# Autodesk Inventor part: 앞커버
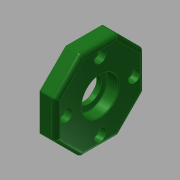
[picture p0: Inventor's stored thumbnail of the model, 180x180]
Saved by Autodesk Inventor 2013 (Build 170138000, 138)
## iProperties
Created: 2015-11
Part Number: 앞커버
Material: 알루미늄 6061
Document SubType Name: Modeling
Designer: mduedu
Density: 2.71 g/cm^3
Mass: 74.9225 g
Surface Area: 93.0141 cm^2
Volume: 27.6467 cm^3
Author: mduedu
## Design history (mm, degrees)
sketch "스케치5" dims "d66" = 60
  geometry: L1 (12.426, 30)-(30, 12.426); L2 (30, 12.426)-(30, -12.426); L3 (30, -12.426)-(12.426, -30); L4 (12.426, -30)-(-12.426, -30); L5 (-12.426, -30)-(-30, -12.426); L6 (-30, -12.426)-(-30, 12.426); L7 (-30, 12.426)-(-12.426, 30); L8 (-12.426, 30)-(12.426, 30); 4 further points
  constraints: 16 end point, 2 coincident, 2 vertical alignment, 1 midpoint, 19 other
extrude "돌출2" new body sketch "스케치5" distance "d67" = 11; taper "d68" = 0 deg
sketch "스케치6"
  geometry: C1 r 16 at (0, 0); 1 further point
  constraints: 1 centre point, 1 coincident
  dimensions: "d69" = 32 diameter of C1
extrude "돌출3" join sketch "스케치6" distance "d70" = 3; taper "d71" = 0 deg
hole "구멍7" diameter "d98" = 25; stored, may be unused: countersink angle "d102" = 90 deg, drill point angle "d104" = 0 deg; dims "d96" = 10, "d97" = 10, "d99" = 6, "d100" = 4, "d101" = 2, "d103" = 3
hole "구멍8" diameter "d107" = 25; stored, may be unused: countersink angle "d111" = 90 deg, drill point angle "d113" = 0 deg; dims "d105" = 10, "d106" = 10, "d108" = 6, "d109" = 4, "d110" = 2, "d112" = 7.7
hole "구멍9" diameter "d116" = 17; stored, may be unused: countersink angle "d120" = 90 deg, drill point angle "d122" = 0 deg; dims "d114" = 10, "d115" = 10, "d117" = 6, "d118" = 4, "d119" = 2, "d121" = 7.7
chamfer "모따기2" distance "d123" = 0.6; stored, may be unused: second distance "d124" = 2, angle "d125" = 30 deg
fillet "모깎기11" dims "d126" = 0.3
fillet "모깎기12" dims "d127" = 1
fillet "모깎기13" dims "d128" = 3
fillet "모깎기14" dims "d129" = 3
fillet "모깎기15" dims "d130" = 0.3
sketch "스케치8" dims "d131" = 46
  geometry: 3 further points
  constraints: 2 vertical alignment, 1 coincident, 2 other
hole "구멍10" sketch "스케치8" at (0, 23) diameter "d132" = 4.5; stored, may be unused: countersink angle "d136" = 90 deg, drill point angle "d138" = 0 deg; dims "d133" = 6, "d134" = 8, "d135" = 4.6, "d137" = 7.7
node "솔리드2"
pattern_circular "원형 패턴4" dims angle "d140" = 360 deg
